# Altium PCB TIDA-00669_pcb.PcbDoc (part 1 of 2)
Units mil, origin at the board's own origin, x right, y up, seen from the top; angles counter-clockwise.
Board outline 2510.03 x 1760.03 mil, 2 copper layers (Top Layer, Bottom Layer), stack 62 mil thick; 109 components, 52 nets, 337 pads, 6 vias.
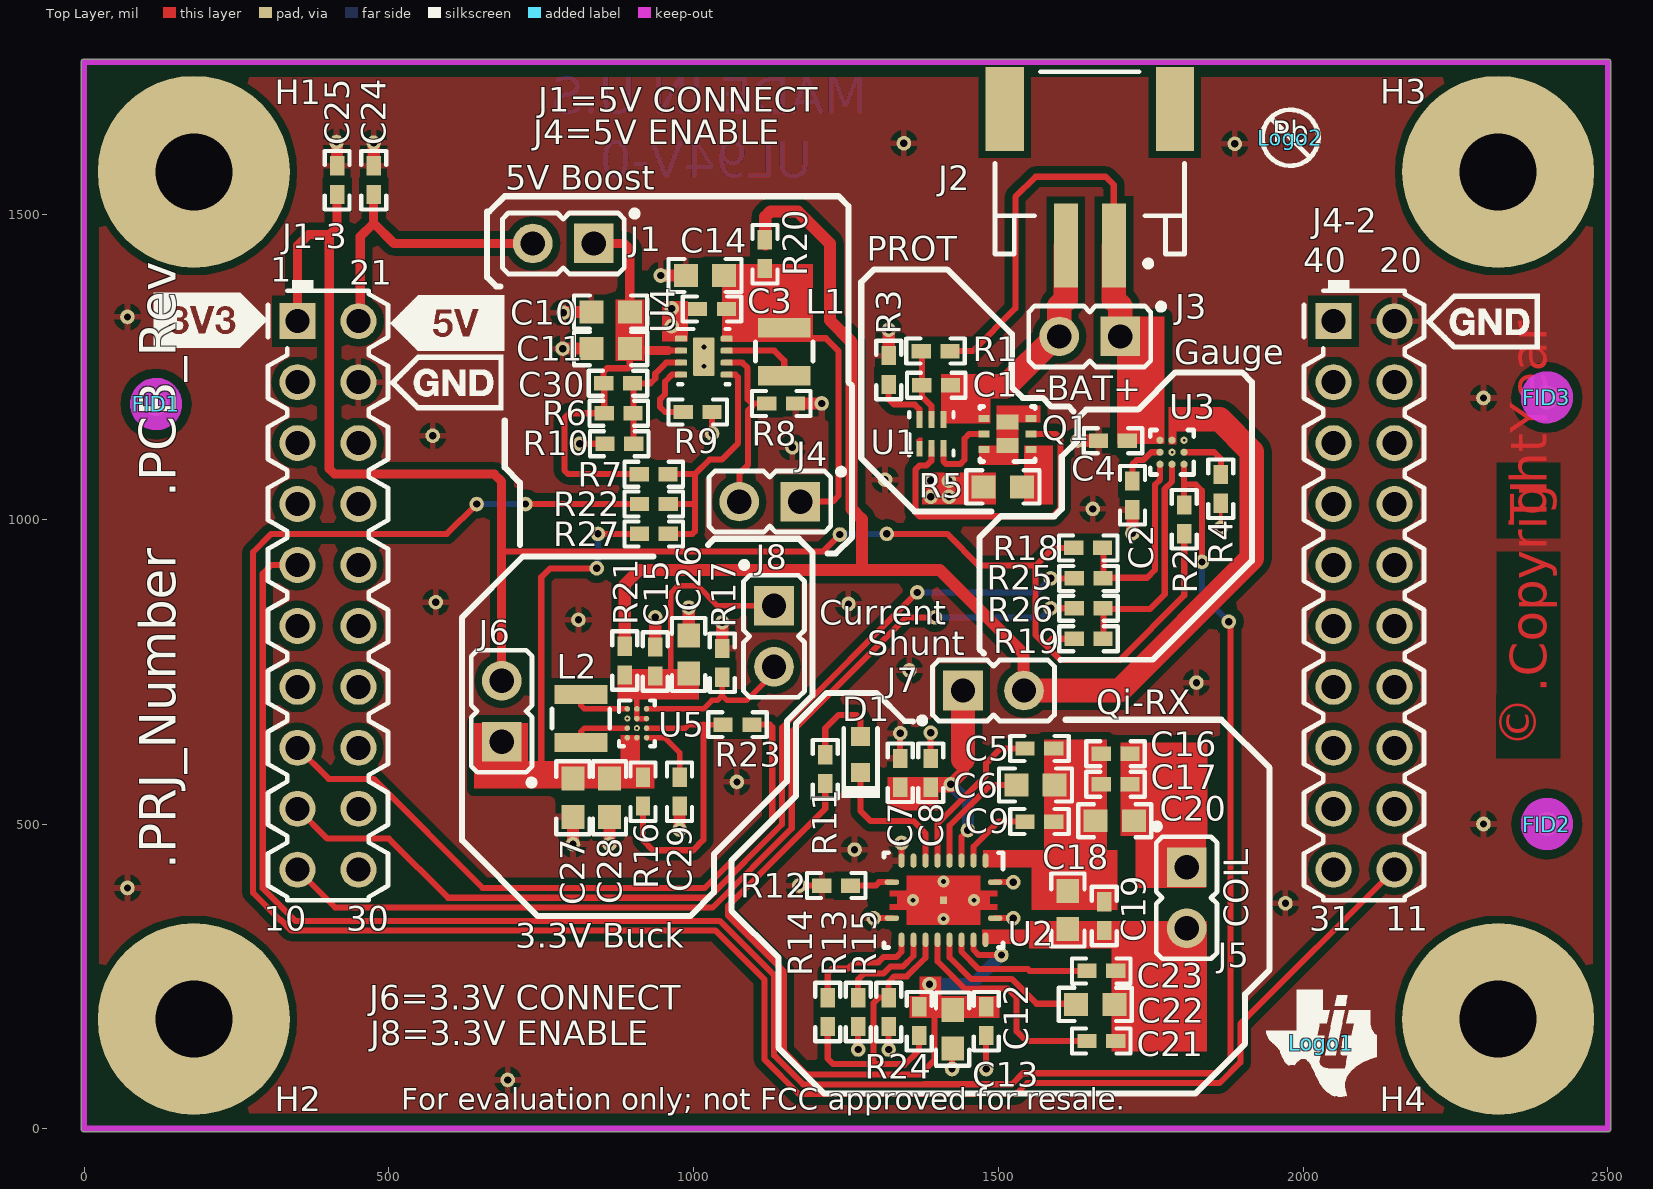
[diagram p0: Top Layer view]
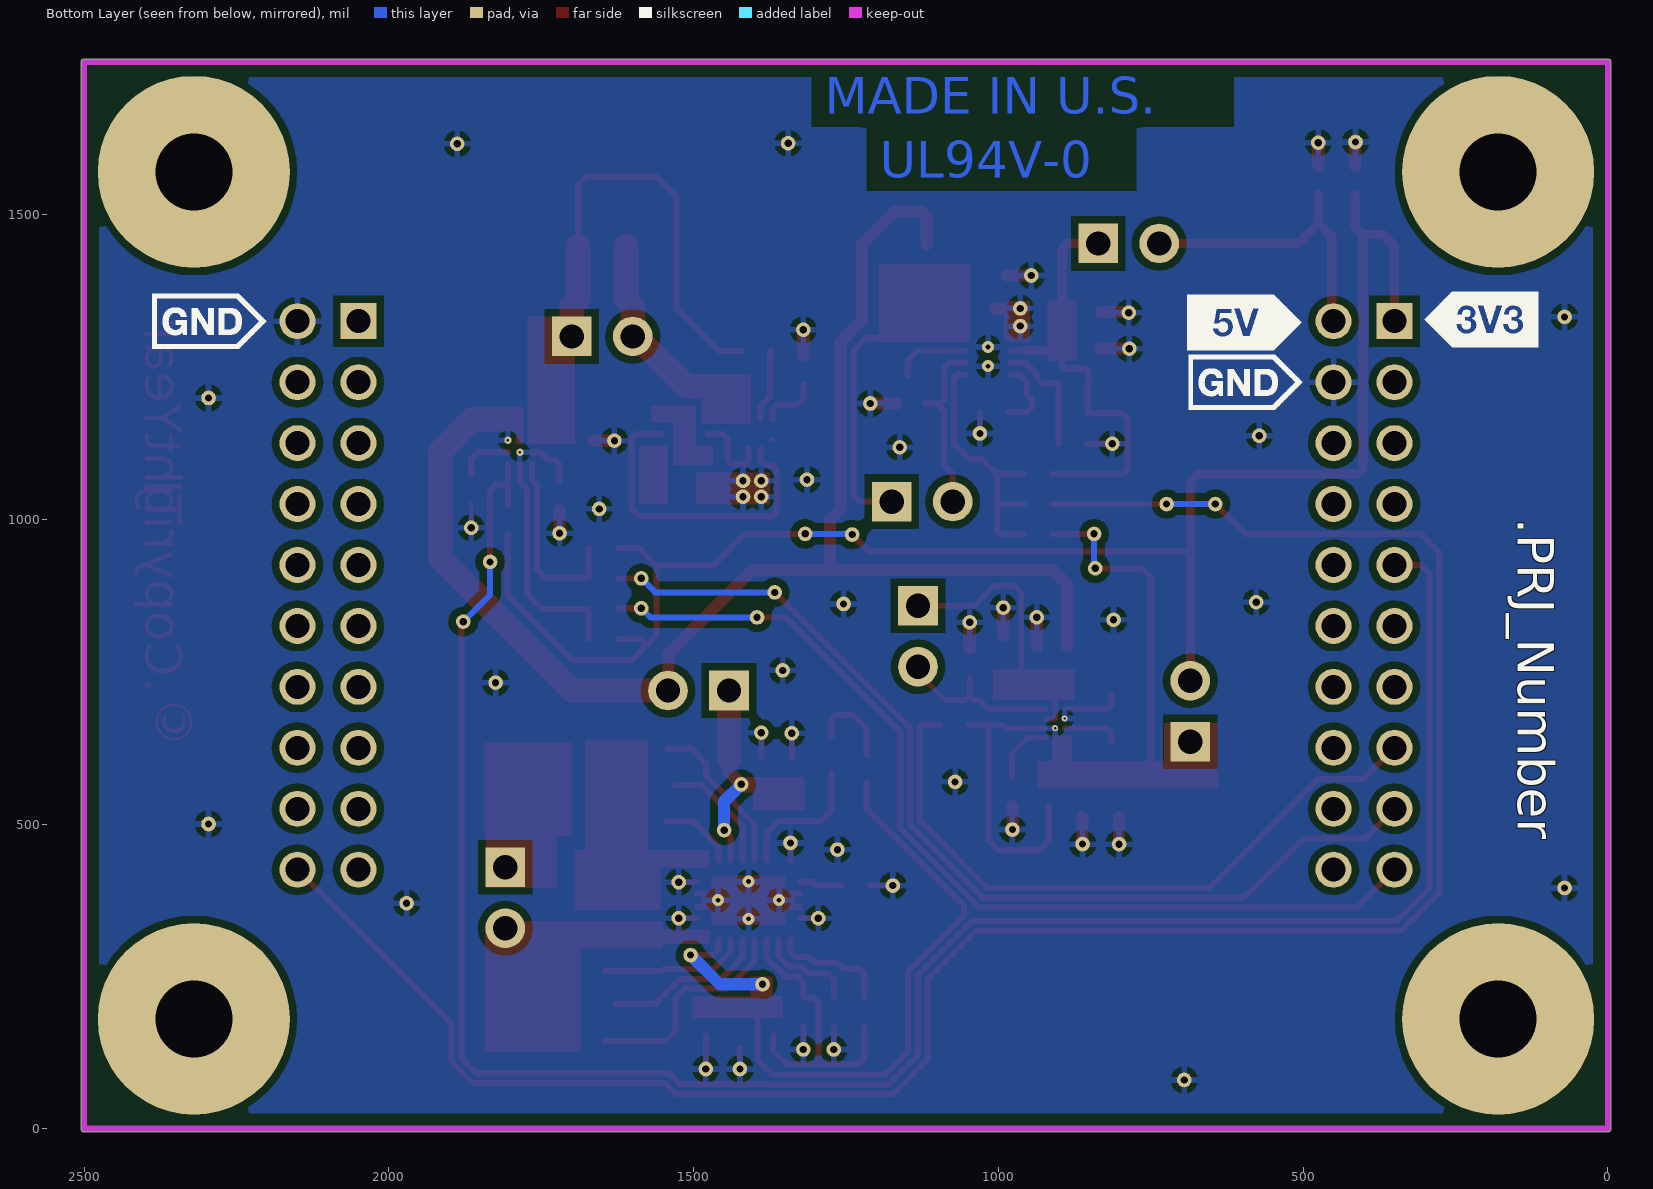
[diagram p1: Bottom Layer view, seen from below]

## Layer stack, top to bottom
Top Solder: solder mask 0.4, Solder Resist, Dk 3.5
Top Layer: signal copper 1.4
Dielectric1: core 59.2, FR-4, Dk 4.8
Bottom Layer: signal copper 1.4
Bottom Solder: solder mask 0.4, Solder Resist, Dk 3.5

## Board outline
0,-5.02 cw(c0,0) -5.01,0 -5.01,1750 cw(c0,1750) 0,1755.01 2500,1755.01 cw(c2500,1750) 2505.01,1750 2505.01,0 cw(c2500,0) 2500,-5.02

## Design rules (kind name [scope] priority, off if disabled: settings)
AcuteAngle [All] p1: minimum=4.50000000000000E+0001 checktracksonly=FALSE
AssemblyTestPointUsage [All] p1: valid=2
Clearance Clearance_Keepouts [((IsTrack Or IsArc) And Not InPoly) And IsFree and IsKeepOut vs ((IsTrack Or IsArc) And Not InPoly) And IsFree and IsKeepOut] p1: gap=0
Clearance Clearance_BoardEdge_MountingHoles [OnCopper and InComponentClass('Mounting Holes') vs IsKeepOut] p2: gap=15
Clearance Clearance_BoardEdge_Poly [OnCopper and InPoly vs IsKeepOut] p3: gap=15
Clearance Clearance_BoardEdge [OnCopper and Not InComponentClass('Logo') and not InComponentClass('FiducialMark') and not InRegion(1000,500,4000,800) and Not IsKeepout vs IsKeepOut] p4: gap=40
Clearance Clearance_Poly [InPolygon] p5: gap=12
Clearance [All] p6: gap=6
ComponentClearance ComponentClearance_MountingHoles_FiducialMarks [InComponentClass('Mounting Holes') vs InComponentClass('FiducialMark')] p1: gap=50 collisioncheckmode=3 verticalgap=10 showdistances=FALSE
ComponentClearance ComponentClearance_Shunt [InComponentClass('Header') vs InComponentClass('Shunt')] p2: gap=0 collisioncheckmode=3 verticalgap=0 showdistances=FALSE
ComponentClearance ComponentClearance_Logo [InComponentClass('Logo')] p3: gap=50 collisioncheckmode=3 verticalgap=10 showdistances=FALSE
ComponentClearance ComponentClearance_ScrewToNut [(HasFootprint('NY PMS 440 0025 PH')) vs (HasFootprint('Keystone_1902C'))] p4: gap=5 collisioncheckmode=3 verticalgap=10 showdistances=FALSE
ComponentClearance ComponentClearance_MountingHoles [InComponentClass('Mounting Holes')] p5: gap=20 collisioncheckmode=3 verticalgap=100000 showdistances=FALSE
ComponentClearance ComponentClearance_SmallPassives [HasFootprint('0201*') or HasFootprint('0402*') or HasFootprint('0508') or HasFootprint('0603*') or HasFootprint('0612') or HasFootprint('0805*') or HasFootprint('0815*') or HasFootprint('0830*') or HasFootprint('1206*') or HasFootprint('1210*') or HasFootprint('1808*') or HasFootprint('1812*') or HasFootprint('1825*') or HasFootprint('2010*') or HasFootprint('2220*') or HasFootprint('2225*') or HasFootprint('2512*') or HasFootprint('2728*') or HasFootprint('3518*') vs HasFootprint('0201*') or HasFootprint('0402*') or HasFootprint('0508') or HasFootprint('0603*') or HasFootprint('0612') or HasFootprint('0805*') or HasFootprint('0815*') or HasFootprint('0830*') or HasFootprint('1206*') or HasFootprint('1210*') or HasFootprint('1808*') or HasFootprint('1812*') or HasFootprint('1825*') or HasFootprint('2010*') or HasFootprint('2220*') or HasFootprint('2225*') or HasFootprint('2512*') or HasFootprint('2728*') or HasFootprint('3518*')] p6: gap=12 collisioncheckmode=3 verticalgap=12 showdistances=FALSE
ComponentClearance ComponentClearance_THtoSMT [IsThruComponent vs IsSMTComponent] p7: gap=12 collisioncheckmode=3 verticalgap=12 showdistances=FALSE
ComponentClearance ComponentClearance_THtoTH [IsThruComponent vs IsThruComponent] p8: gap=12 collisioncheckmode=3 verticalgap=12 showdistances=FALSE
ComponentClearance [All] p9: gap=12 collisioncheckmode=3 verticalgap=12 showdistances=FALSE
DiffPairsRouting [All] p1: maxlimit=100 minlimit=10 mostfreqgap=10 toplayer_minwidth=15 toplayer_maxwidth=15 toplayer_prefwidth=15 bottomlayer_minwidth=15 bottomlayer_maxwidth=15 bottomlayer_prefwidth=15 maxuncoupledlength=1000
FabricationTestPointUsage TestPointUsage [All] p1: valid=2 allowmultiple=FALSE
FabricationTestpoint Testpoint [All] p1: side=3 testpointundercomponent=TRUE minsize=40 maxsize=100 preferedsize=60 minholesize=0 maxholesize=40 preferedholesize=32 testpointgrid=1 allowsidetop=TRUE allowsidebottom=TRUE usegrid=TRUE gridtolerance=0.01
FanoutControl Fanout_LCC [IsLCC] p1: bgadir=Out bgaviamode=Centered fanoutstyle=Auto fanoutdirection=Alternating viagrid=1 // Fanout_LCC (Default Rule)
FanoutControl Fanout_BGA [IsBGA] p2: bgadir=Out bgaviamode=Centered fanoutstyle=Auto fanoutdirection=Alternating viagrid=1 // Fanout_BGA (Default Rule)
FanoutControl Fanout_Default [All] p4: bgadir=Out bgaviamode=Centered fanoutstyle=Auto fanoutdirection=Alternating viagrid=1 // Fanout_Default (Default Rule)
FanoutControl Fanout_Small [(CompPinCount < 5)] p5: bgadir=Out bgaviamode=Centered fanoutstyle=Auto fanoutdirection=OutThenIn viagrid=1 // Fanout_Small (Default Rule)
HoleSize [All] p1: absolutevalues=TRUE maxlimit=251 minlimit=8 maxpercent=80.000 minpercent=20.000
MinimumAnnularRing MinimumAnnularRing_ThermalPadVias [IsVia and InAnyComponent] p1: minimumring=5.91
MinimumAnnularRing [All] p2: minimumring=9
MinimumSolderMaskSliver MinimumSolderMaskSliver_Logo [InComponentClass('Logo') vs InComponentClass('Logo')] p1: minsoldermaskwidth=0.7
MinimumSolderMaskSliver [All] p2: minsoldermaskwidth=3.94
PlaneConnect [All] p1: planeconnectstyle=Relief reliefexpansion=10 reliefentries=4 reliefconductorwidth=10 reliefairgap=10
PolygonConnect [All] p1: connectstyle=Relief reliefconductorwidth=10 reliefentries=4 polygonreliefangle="90 Angle" airgapwidth=10
RoutingVias ThermalPadVias [IsVia and InAnyComponent] p1: holewidth=7.87 width=19.68 viastyle="Through Hole" minholewidth=7.87 minwidth=19.68 maxholewidth=12.99 maxwidth=23.62
RoutingVias [All] p2: holewidth=16 width=34 viastyle="Through Hole" minholewidth=7.87 minwidth=26 maxholewidth=40 maxwidth=65
SilkToBoardRegionClearance [Not ((IsComment or IsDesignator) And (Hide <> 'False')) and not InRegion(1000,500,4000,800)] p1:
SilkToSilkClearance SilkToSilkClearance_Pb-FreeLogo [(HasFootprint('Pb-Free_Overlay_Medium') OR HasFootprint('Pb-Free_Overlay_Small')) vs (HasFootprint('Pb-Free_Overlay_Medium') OR HasFootprint('Pb-Free_Overlay_Small'))] p1: silktosilkclearance=0
SilkToSilkClearance [All] p2: silktosilkclearance=5
SilkToSolderMaskClearance "Silk to Solder Mask Opening" [All] p1: minsilkscreentomaskgap=1 clearancetoexposedcopper=FALSE
SolderMaskExpansion [All] p1: expansion=1.97
UnpouredPolygon [All] p1: allowunpoured=FALSE
Width [All] p1: maxlimit=100 minlimit=6 preferedwidth=10 checkconnectedcopper=TRUE
14 further rules are at their usual default settings.

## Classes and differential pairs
component class EMI: "Coil 1" "Ferrite 1"
component class AssemblyNote: ZZ1 ZZ2 ZZ3 ZZ4 ZZ5 ZZ6 ZZ7 ZZ8
component class FiducialMark: FID1 FID2 FID3
component class TIDA-00669_hdw: "Coil 1" "Ferrite 1" FID1 FID2 FID3 H1 H2 H3 H4 H5 H6 H7 H8 HS1 HS2 HS3 HS4 Logo1 Logo2 Logo3 SH-J1 SH-J4 SH-J6 SH-J7 SH-J8 ZZ1 ZZ2 ZZ3 ZZ4 ZZ5 ZZ6 ZZ7 ZZ8
component class Logo: Logo1
component class TIDA-00669_sch: C1 C2 C3 C4 C5 C6 C7 C8 C9 C10 C11 C12 C13 C14 C15 C16 C17 C18 C19 C20 C21 C22 C23 C24 C25 C26 C27 C28 C29 C30 D1 J1 J1-3 J2 J3 J4 J4-2 J5 J6 J7 J8 L1 L2 Q1 R1 R2 R3 R4 R5 R6 R7 R8 R9 R10 R11 R12 R13 R14 R15 R16 R17 R18 R19 R20 R21 R22 R23 R24 R25 R26 R27 U1 U2 U3 U4 U5
component class Header: J1 J1-3 J3 J4 J4-2 J5 J6 J7 J8
component class "Mounting Holes": H1 H2 H3 H4 H5 H6 H7 H8
component class Shunt: SH-J1 SH-J4 SH-J6 SH-J7 SH-J8

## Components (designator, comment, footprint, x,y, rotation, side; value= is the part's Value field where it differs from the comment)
C1 "GRM155R71A104KA01D" 0402 1398,1220 r0 top
C2 "GRM155R60J474KE19D" 0402 1720,1039.38 r270 top
C3 "GRM155R71A104KA01D" 0402 1030.08,1345 r180 top
C4 "GRM155R61A105KE15D" 0402 1688,1129 r180 top
C5 "GRM155R71H223KA12D" 0402 1567.38,623.94 r0 top
C6 "GRM188R71E474KA12D" 0603 1560.88,563.94 r0 top
C7 "GRM155R71A104KA01D" 0402 1338.94,583.94 r90 top
C8 "C1005X5R1A475K050BC" 0402 1388.94,583.94 r90 top
C9 "C0402C103J5RACTU" 0402 1567.38,503.94 r0 top
C10 "C0603C106M9PACTU" 0603 863.7,1340 r180 top
C11 "C0603C106M9PACTU" 0603 863.7,1280 r180 top
C12 "C1005X7R1C223K" 0402 1480,176.38 r270 top
C13 "GRM188R61C475KAAJ" 0603 1425,163.5 r270 top
C14 "C0603C106M9PACTU" 0603 1018.7,1400 r180 top
C15 "GRM155R71A104KA01D" 0402 936.92,766.7 r90 top
C16 "C1005X7R1H683K" 0402 1692.38,615.26 r0 top
C17 "C1005X7R1H683K" 0402 1692.38,565.26 r0 top
C18 "GRM1885C1H182JA01D" 0603 1613.94,358.94 r270 top
C19 "CC0402JRNPO9BN101" 0402 1673.94,348.94 r90 top
C20 "GRM188R71H473KA61D" 0603 1690.88,505.26 r0 top
C21 "GRM155R71H223KA12D" 0402 1668.94,143.94 r0 top
C22 "GRM188R71E474KA12D" 0603 1658.94,203.94 r0 top
C23 "C0402C103J5RACTU" 0402 1668.94,258.94 r0 top
C24 "GRM155R71A104KA01D" 0402 475,1556.38 r90 top
C25 "GRM155R71A104KA01D" 0402 415,1556.38 r90 top
C26 "C0603C106M9PACTU" 0603 991.92,778.08 r90 top
C27 "C0603C106M9PACTU" 0603 801.92,543.08 r270 top
C28 "C0603C106M9PACTU" 0603 861.92,543.08 r270 top
C29 "0402YC132KAT2A" 0402 976.92,553.08 r270 top
C30 "CC0402JRNPO9BN101" 0402 876,1223 r0 top
"Coil 1" "760308103206" SIL-PAD_24X21MM 1500,7360 r90 top
D1 "LTST-C190GKT" LED_LTST-C190 1273.94,613.94 r270 top
"Ferrite 1" "354005" SIL-PAD_24X21MM 2440,7370 r90 top
FID1 "Fiducial" Fiducial10-20 118,1189 r0 top
FID2 "Fiducial" Fiducial10-20 2400,500 r0 top
FID3 "Fiducial" Fiducial10-20 2400,1200 r0 top
H1 "NY PMS 440 0025 PH" "NY PMS 440 0025 PH" 180,1570 r0 top locked
H2 "NY PMS 440 0025 PH" "NY PMS 440 0025 PH" 180,180 r0 top locked
H3 "NY PMS 440 0025 PH" "NY PMS 440 0025 PH" 2320,1570 r0 top locked
H4 "NY PMS 440 0025 PH" "NY PMS 440 0025 PH" 2320,180 r0 top locked
H5 "NY PMS 440 0025 PH" "NY PMS 440 0025 PH" 1150.36,3190 r180 top
H6 "NY PMS 440 0025 PH" "NY PMS 440 0025 PH" 128.36,3186 r180 top
H7 "NY PMS 440 0025 PH" "NY PMS 440 0025 PH" 468.36,3186 r180 top
H8 "NY PMS 440 0025 PH" "NY PMS 440 0025 PH" 818.36,3186 r180 top
HS1 "1902B" Keystone_1902B 200,2750 r0 top
HS2 "1902B" Keystone_1902B 550,2750 r0 top
HS3 "1902B" Keystone_1902B 900,2750 r0 top
HS4 "1902B" Keystone_1902B 1250,2750 r0 top
J1 "PBC02SAAN" Sullins_PBC02SAAN 786.16,1452.58 r270 top
J1-3 "PRPC010DAAN-RC" Sullins_xxxC010DAAN 400,875 r0 top
J2 "S2B-PH-SM4-TB(LF)(SN)" JST_S2B-PH-SM4-TB 1650,1565 r180 top
J3 "PBC02SAAN" Sullins_PBC02SAAN 1650,1300 r270 top
J4 "PBC02SAAN" Sullins_PBC02SAAN 1125,1029 r270 top
J4-2 "PRPC010DAAN-RC" Sullins_xxxC010DAAN 2100,875 r0 top
J5 "PBC02SAAN" Sullins_PBC02SAAN 1808.94,378.94 r0 top
J6 "PBC02SAAN" Sullins_PBC02SAAN 685,685 r180 top
J7 "PBC02SAAN" Sullins_PBC02SAAN 1492,719 r90 top
J8 "PBC02SAAN" Sullins_PBC02SAAN 1131.92,808.08 r0 top
L1 "LQM2HPN1R5MG0L" 1008 1148.7,1275 r270 top
L2 "LQM2HPN1R5MG0L" 1008 815,673 r270 top
Logo1 "Texas Instruments" TI_Symbol_Overlay_Small 2030,140 r0 top
Logo2 "Pb-Free Symbol" Pb-Free_Overlay_Small 1979,1626 r0 top
Logo3 "FCC disclaimer" FCC_disclaimer 150,-560 r90 top
Q1 "CSD85301Q2" DQK0006B 1515,1140 r180 top
R1 "CRCW0402221RFKED" 0402 1397,1276 r0 top
R2 "CRCW040210K0FKED" 0402 1805,1000 r270 top
R3 "CRCW04022K21FKED" 0402 1320,1245 r270 top
R4 "CRCW040210K0FKED" 0402 1865,1050 r90 top
R5 "ERJ-L03KF47MV" 0603 1507.5,1053 r0 top
R6 "CRCW0402768KFKED" 0402 877,1174 r180 top
R7 "CRCW04021M00FKED" 0402 934.38,1074 r180 top
R8 "CRCW04021M00FKED" 0402 1143.7,1190 r180 top
R9 "CRCW040212K4FKED" 0402 1006.62,1176 r0 top
R10 "CRCW0402243KFKED" 0402 878,1124 r0 top
R11 "CRCW04021K50FKED" 0402 1216,590 r270 top
R12 "CRCW04022K43FKED" 0402 1233.94,398.94 r0 top
R13 "CRCW040210K0FKED" 0402 1270,191.38 r90 top
R14 "CRCW0402422RFKED" 0402 1220,191.38 r90 top
R15 "CRCW0402200RFKED" 0402 1320,191.38 r90 top
R16 "CRCW04021M00FKED" 0402 916.92,553.08 r270 top
R17 "CRCW04021M00FKED" 0402 1046.92,764.46 r270 top
R18 "CRCW04021K00FKED" 0402 1647.38,953 r180 top
R19 "CRCW04021K00FKED" 0402 1648,804 r180 top
R20 "CRCW04020000Z0ED" 0402 1117,1435 r270 top
R21 "CRCW04020000Z0ED" 0402 886.92,768.08 r270 top
R22 "CRCW04020000Z0ED" 0402 934.62,1025 r180 top
R23 "CRCW04020000Z0ED" 0402 1071.92,663.08 r0 top
R24 "CRCW040220K0FKED" 0402 1370,176.38 r90 top
R25 "CRCW04020000Z0ED" 0402 1648,903 r180 top
R26 "CRCW04020000Z0ED" 0402 1648,854 r180 top
R27 "CRCW04021M00FKED" 0402 934.62,976 r0 top
SH-J1 "969102-0000-DA" SNT-100-BK-G 120,3640 r90 top
SH-J4 "969102-0000-DA" SNT-100-BK-G 470,3640 r90 top
SH-J6 "969102-0000-DA" SNT-100-BK-G 820,3640 r90 top
SH-J7 "969102-0000-DA" SNT-100-BK-G 1170,3640 r90 top
SH-J8 "969102-0000-DA" SNT-100-BK-G 1520,3640 r90 top
U1 "BQ29707DSER" DSE0006A 1390,1140 r90 top
U2 "BQ51050BRHL" RHL0020A 1410,375 r270 top
U3 "BQ27421YZFR-G1A" YZF0009AKAL 1785,1110 r180 top
U4 "TPS61252DSG" DSG0008A 1016.8,1266.86 r0 top
U5 "TPS63051YFF" YFF0012AFAF 906.92,665.21 r0 top
ZZ1 "These assemblies are ESD sensitive, ESD precautions shall be observed." AssemblyNote 1125,6730 r0 top
ZZ2 "These assemblies must be clean and free from flux and all contaminants. Use of no clean flux is not acceptable." AssemblyNote 1095,6635 r0 top
ZZ3 "These assemblies must comply with workmanship standards IPC-A-610 Class 2, unless otherwise specified." AssemblyNote 1100,6540 r0 top
ZZ4 "Wireless Coil 1 will be attached to the PCB C02 on the bottom of the board stack. The wires will be soldered to the PCB." AssemblyNote 1145,6460 r0 top
ZZ5 "The Ferrite Shield must be custom cut to fit the PCB. Only the four mounting holes are allowed." AssemblyNote 1120,6330 r0 top
ZZ6 "Nylon screws and spacers only for this assembly. The only copper on PCB C01 and C02 is for the wire holes. No extra copper is allowed on PCB C01 and C02." AssemblyNote 1105,6245 r0 top
ZZ7 "Use 2 strands, 3 inch Length, of 26 gauge litz wire to connect the PCB C01 board to the main PCB connector J3. Attach the litz wire to PCB C02 and leave hanging." AssemblyNote 1150,6130 r0 top
ZZ8 "The assembly build will use PCB C01. Bag and ship PCB C02 with the assembly." AssemblyNote 1145,6010 r0 top

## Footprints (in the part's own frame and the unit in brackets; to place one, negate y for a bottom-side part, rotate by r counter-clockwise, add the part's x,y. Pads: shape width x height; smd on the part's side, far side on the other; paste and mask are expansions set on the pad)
0402 [mm] "0402 from SM-752 data"
  rect 0.8x0.6 smd: 1(-0.6,0) 2(0.6,0)
  silkscreen extent -1.22,-0.52 1.22,0.52, body extent -0.55,-0.3 0.55,0.3, height 0.6
0603 [mm] "0603 from SM-752 data"
  rect 1x0.95 smd: 1(-0.8,0) 2(0.8,0)
  silkscreen extent -1.52,-0.69 1.52,0.69, body extent -0.87,-0.47 0.87,0.47, height 0.85
1008 [mm] "SMD, Body 2.5x2mm, Height 1.2mm"
  rect 0.8x2.2 smd: 1(-1,0) 2(1,0)
  silkscreen extent -0.4,-1.2 0.4,1.2, body extent -1.35,-1.1 1.35,1.1, height 1.2
AssemblyNote [mil] "Assembly Note"
DQK0006B [mm] "TI"
  rect 0.45x0.3 smd: 1(-0.975,0.65) 2(-0.975,0) 3(-0.975,-0.65) 4(0.975,-0.65) 5(0.975,0) 6(0.975,0.65)
  rect 0.9x0.625 smd paste-0.025: 7(0,0.488) 8(0,-0.488)
  silkscreen extent -1.15,-1.15 1.15,1.15, body extent -1.05,-1.05 1.05,1.05, height 0.8
DSE0006A [mm] "TI recommended land pattern"
  rect 0.66x0.25 smd: 1(-0.62,0.5)
  rect 0.7x0.25 smd: 2(-0.6,0) 3(-0.6,-0.5) 4(0.6,-0.5) 5(0.6,0) 6(0.6,0.5)
  Top Layer region: -0.3,0.625 -0.25,0.625 -0.15,0.525 -0.15,0.375 -0.3,0.375
  silkscreen extent -0.9,-0.92 0.9,0.92, body extent -0.77,-0.77 0.77,0.77, height 0.8
DSG0008A [mm] "SON, 8-Leads, Body 2x2mm, Pitch 0.5mm, Thermal Pad 1.6x0.9mm, TI Recommended"
  rrect40% 0.5x0.25 smd: 1(-0.95,0.75) 2(-0.95,0.25) 3(-0.95,-0.25) 4(-0.95,-0.75) 5(0.95,-0.75) 6(0.95,-0.25) 7(0.95,0.25) 8(0.95,0.75)
  rrect11% 0.9x1.6 smd paste-0.45: 9(0,0)
  silkscreen extent -1.07,-1.15 1.07,1.15, body extent -1.05,-1.05 1.05,1.05, height 0.8
FCC_disclaimer [mil]
Fiducial10-20 [mm]
  round 1 smd mask+0.5: 1(0,0)
  Top Layer keep-out circle w1.178: c0,0 r0.5
JST_S2B-PH-SM4-TB [mm] "JST Sales America Inc"
  rect 1x3.5 smd paste+0 mask+0.05: 1(-1,2.95) 2(1,2.95)
  rect 1.6x3.5 smd paste+0 mask+0.05: M1(-3.55,-2.75) M2(3.55,-2.75)
  silkscreen extent -3.95,-4.3 3.95,3.79, body extent -3.95,-4.3 3.95,4.3, height 5.62
Keystone_1902B [mil] "Hex Standoff, 4-40 threaded, nylon"
  round 1 on Mech3: 0(0,0)
  body extent -145,-126 145,126, height 375
LED_LTST-C190 [mm] "Lite-On"
  rect 0.8x0.8 smd: 1(-0.75,0) 2(0.75,0)
  silkscreen extent -1.1,-0.8 1.8,0.8, body extent -0.85,-0.45 0.85,0.45, height 0.9
"NY PMS 440 0025 PH" [mm] "4-40 nylon screw and mounting hole"
  round 8 hole 3.2: 1(0,0)
  body extent -3.3,-3.3 3.3,3.3, height 2.69
Pb-Free_Overlay_Small [mil]
  silkscreen extent -46,-46 46,46
RHL0020A [mm] "QFN, 20-Leads, Body 4.5x3.5mm, Pitch 0.5mm, Thermal Pad 3.05x2.05mm, TI Recommended"
  oval 0.24x0.6 smd: 1(-0.75,2.15) 10(-0.75,-2.15) 11(0.75,-2.15) 20(0.75,2.15)
  oval 0.6x0.24 smd: 2(-1.65,1.75) 3(-1.65,1.25) 4(-1.65,0.75) 5(-1.65,0.25) 6(-1.65,-0.25) 7(-1.65,-0.75) 8(-1.65,-1.25) 9(-1.65,-1.75) 12(1.65,-1.75) 13(1.65,-1.25) 14(1.65,-0.75) 15(1.65,-0.25) 16(1.65,0.25) 17(1.65,0.75) 18(1.65,1.25) 19(1.65,1.75)
  rect 0.3x0.3 smd paste-0.15 mask+0: 21(0,0)
  Top Layer region: 0.16,2.25 0.16,1.925 -0.16,1.925 -0.16,2.25 -0.39,2.25 -0.39,1.525 -1.025,1.525 -1.025,-1.525 -0.39,-1.525 -0.39,-2.25 -0.16,-2.25 -0.16,-1.925 0.16,-1.925 0.16,-2.25 0.39,-2.25 0.39,-1.525 1.025,-1.525 1.025,1.525 0.39,1.525 0.39,2.25
  silkscreen extent -1.98,-2.47 1.98,2.47, body extent -1.82,-2.33 1.83,2.32, height 1.01
SIL-PAD_24X21MM [mil] "Sil-Pad"
  silkscreen extent -482,-423 482,423, body extent -472,-413 472,413, height 9
SNT-100-BK-G [mil] "Samtec STEP model"
  round 1 on Mech3: 0(0,0)
  body extent -100,-50 100,50, height 344
Sullins_PBC02SAAN [mm] "Sullins 100mil, 1x2, 230 mil above insulator"
  rect 1.65x1.65 hole 1.016: 1(0,1.27)
  round 1.65 hole 1.016: 2(0,-1.27)
  silkscreen extent -1.37,-2.54 1.27,3.1, body extent -1.27,-2.54 1.27,2.54, height 8.38
Sullins_xxxC010DAAN [mm] "Header, 2.54mm, 10x2, TH"
  rect 1.5x1.5 hole 1: 1(-1.27,11.43)
  round 1.5 hole 1: 2(1.27,11.43) 3(-1.27,8.89) 4(1.27,8.89) 5(-1.27,6.35) 6(1.27,6.35) 7(-1.27,3.81) 8(1.27,3.81) 9(-1.27,1.27) 10(1.27,1.27) 11(-1.27,-1.27) 12(1.27,-1.27) 13(-1.27,-3.81) 14(1.27,-3.81) 15(-1.27,-6.35) 16(1.27,-6.35) 17(-1.27,-8.89) 18(1.27,-8.89) 19(-1.27,-11.43) 20(1.27,-11.43)
  silkscreen extent -2.5,-12.7 2.5,13.14, body extent -2.5,-12.7 2.5,12.7, height 8.34
TI_Symbol_Overlay_Small [mil]
  silkscreen extent -90,-88 91,88
YFF0012AFAF [mm] "TI DSBGA 1.716x1.316mm"
  round 0.23 smd paste-0.13 mask+0.038: A1(-0.4,0.6) A2(0,0.6) A3(0.4,0.6) B1(-0.4,0.2) B2(0,0.2) B3(0.4,0.2) C1(-0.4,-0.2) C2(0,-0.2) C3(0.4,-0.2) D1(-0.4,-0.6) D2(0,-0.6) D3(0.4,-0.6)
  silkscreen extent -0.75,-0.95 0.75,0.95, body extent -0.66,-0.86 0.66,0.86, height 0.63
YZF0009AKAL [mm] "BGA, 9-Leads, Body 1.6205x1.58mm, Pitch 0.5mm"
  round 0.3 smd paste-0.15 mask+0.05: A1(-0.5,0.5) A2(0,0.5) A3(0.5,0.5) B1(-0.5,0) B2(0,0) B3(0.5,0) C1(-0.5,-0.5) C2(0,-0.5) C3(0.5,-0.5)
  silkscreen extent -0.9,-0.93 0.9,0.93, body extent -0.8,-0.83 0.8,0.83, height 0.63

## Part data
C1 C3 C7 C15 C24 C25: "CAP, CERM, 0.1 µF, 10 V, +/- 10%, X7R, 0402"
C2: "CAP, CERM, 0.47 µF, 6.3 V, +/- 10%, X5R, 0402"
C4: "CAP, CERM, 1 µF, 10 V, +/- 10%, X5R, 0402"
C5 C21: "CAP, CERM, 0.022 µF, 50 V, +/- 10%, X7R, 0402"
C6 C22: "CAP, CERM, 0.47 µF, 25 V, +/- 10%, X7R, 0603"
C8: "CAP, CERM, 4.7 µF, 10 V, +/- 10%, X5R, 0402"
C9 C23: "CAP, CERM, 0.01 µF, 50 V, +/- 5%, X7R, 0402"
C10 C11 C14 C26 C27 C28: "CAP, CERM, 10 µF, 6.3 V, +/- 20%, X5R, 0603"
C12: "CAP, CERM, 0.022 µF, 16 V, +/- 10%, X7R, 0402"
C13: "CAP, CERM, 4.7 µF, 16 V, +/- 10%, X5R, 0603"
C16 C17: "CAP, CERM, 0.068 µF, 50 V, +/- 10%, X7R, 0402"
C18: "CAP, CERM, 1800 pF, 50 V, +/- 5%, C0G/NP0, 0603"
C19 C30: "CAP, CERM, 100 pF, 50 V, +/- 5%, C0G/NP0, 0402"
C20: "CAP, CERM, 0.047 µF, 50 V, +/- 10%, X7R, 0603"
C29: "CAP, CERM, 1300 pF, 16 V, +/- 10%, X7R, 0402"
"Coil 1": library part SP900S-0.009-00-114, "Wireless coil"
D1: "LED, Green, SMD"
"Ferrite 1": library part SP900S-0.009-00-114, "Ferrite shield"
FID1 FID2 FID3: "Fiducial mark.  There is nothing to buy or mount."
H1 H2 H3 H4 H5 H6 H7 H8: "Machine Screw, Round, #4-40 x 1/4, Nylon, Philips panhead"
HS1 HS2 HS3 HS4: "Standoff, Hex, 0.375\"L #4-40 Nylon"
J1 J3 J4 J5 J6 J7 J8: "Header, 100mil, 2x1, Gold, TH"
J1-3 J4-2: "Header, 2.54mm, 10x2, Gold, TH"
J2: "Header (shrouded), 2mm, 2x1, R/A, SMT"
L1 L2: "Inductor, Multilayer, Ferrite, 1.5 µH, 1.5 A, 0.07 ohm, SMD"
Logo1: library part TI_Logo, "Texas Instrument Corporate Signature"
Logo2: library part Pb-Free
Logo3: library part FCC_disclaimer, "FCC_disclaimer"
Q1: "MOSFET, N-CH, 20 V, 6.7 A,"
R1: "RES, 221, 1%, 0.063 W, 0402"
R2 R4 R13: "RES, 10.0 k, 1%, 0.063 W, 0402"
R3: "RES, 2.21 k, 1%, 0.063 W, 0402"
R5: "RES, 0.047, 1%, 0.1 W, 0603"
R6: "RES, 768 k, 1%, 0.063 W, 0402"
R7 R8 R16 R17 R27: "RES, 1.00 M, 1%, 0.063 W, 0402"
R9: "RES, 12.4 k, 1%, 0.063 W, 0402"
R10: "RES, 243 k, 1%, 0.063 W, 0402"
R11: "RES, 1.50 k, 1%, 0.063 W, 0402"
R12: "RES, 2.43 k, 1%, 0.063 W, 0402"
R14: "RES, 422, 1%, 0.063 W, 0402"
R15: "RES, 200, 1%, 0.063 W, 0402"
R18 R19: "RES, 1.00 k, 1%, 0.063 W, 0402"
R20 R21 R22 R23 R25 R26: "RES, 0, 5%, 0.063 W, 0402"
R24: "RES, 20.0 k, 1%, 0.063 W, 0402"
SH-J1 SH-J4 SH-J6 SH-J7 SH-J8: "Shunt, 100mil, Gold plated, Black"
U1: library part BQ29700DSER, "Cost-Effective Voltage and Current Protection Integrated Circuit for Single-Cell Li-Ion/Li-Polymer Batteries, DSE0006A"
U2: "High-Efficiency Qi v1.1-Compliant Wireless Power Receiver and Battery Charger, RHL0020A"
U3: "System-Side Impedance Track Fuel Gauge With Integrated Sense Resistor, YZF0009AKAL"
U4: "TINY 1.5-A BOOST CONVERTER WITH ADJUSTABLE INPUT CURRENT LIMIT, DSG0008A"
U5: "SINGLE INDUCTOR BUCK-BOOST WITH 1A SWITCHES AND ADJUSTABLE SOFT START, YFF0012AFAF"
ZZ1 ZZ2 ZZ3 ZZ4 ZZ5 ZZ6 ZZ7 ZZ8: library part AssemblyNote

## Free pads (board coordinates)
  round 24 hole 12: 0(71,395) 0(71,1332) 0(414,1619) 0(475,1618) 0(572,1137) 0(577,864) 0(644,1025) 0(695,80) 0(724,1025) 0(785,1280) 0(786,1339) 0(802,467) 0(811,835) 0(813,1124) 0(841,919.53) 0(843,976) 0(861.92,467.08) 0(936.92,839.08) 0(946,1400) 0(964,1317) 0(964,1346) 0(976.92,490.92) 0(991.92,855.08) 0(1030.24,1140.76) 0(1046.92,830.92) 0(1071,569) 0(1162,1118) 0(1173.06,398.94) 0(1210,1190) 0(1240,975) 0(1254,861) 0(1264,458) 0(1270,130) 0(1295.47,345.47) 0(1314,1065) 0(1317,976) 0(1320,130) 0(1320,1311) 0(1338.94,648.94) 0(1341.1,468.9) 0(1345,1617) 0(1354,752) 0(1367,880) 0(1387,237) 0(1388.94,649.94) 0(1389,1037) 0(1389,1063) 0(1396,839) 0(1419,1037) 0(1419,1063) 0(1422,565) 0(1424,98) 0(1450,490) 0(1480,98) 0(1505,285) 0(1524.52,404.52) 0(1524.53,345.47) 0(1586,854) 0(1586,903) 0(1630,1129) 0(1655,1017) 0(1720,977) 0(1825,732) 0(1834,930) 0(1865,986) 0(1878,832) 0(1888,1616) 0(1971,370) 0(2296,500) 0(2296,1199)
  round 10 hole 4: 0(891.17,673.08) 0(906.92,657.33)
  round 12 hole 4: 0(1785,1110) 0(1804.68,1129.68)

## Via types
v1: diameter 19.68, hole 7.87, Top Layer to Bottom Layer, 6 vias

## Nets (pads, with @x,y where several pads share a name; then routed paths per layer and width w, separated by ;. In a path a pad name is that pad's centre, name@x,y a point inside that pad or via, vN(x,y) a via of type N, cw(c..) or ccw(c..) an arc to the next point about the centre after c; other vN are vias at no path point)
+3.3V: C25.1 J1-3.1 J6.2 pad.0@1240,975 pad.0@1317,976 R2.2 R18.2 R19.2 | length 2811.7
  Top Layer w10: 685,947 1212,947 1234,969 pad.0@1240,975 ; pad.0@1317,976 1416,976 1468,924 1561,924 ; R18.2@1623.76,953 1590,953 1561,924 ; R19.2@1624.38,804 1588,804 1577.5,793.5 ; R2.2@1805,976.38 1805,875 1699,769 1602,769 1577.5,793.5 ; 1561,924 1561,810 1577.5,793.5
  Top Layer w15: J1-3.1@350,1325 350,1449 368,1467 402,1467 ; C25.1@415,1532.76 415,1480 402,1467 ; J6.2@685,735 685,947 685,1062 673,1074 411,1074 402,1083 402,1467
  Bottom Layer w10: pad.0@1241,976 pad.0@1317,976
+5V: C24.1 J1-3.2 J1.2 | length 493.1
  Top Layer w15: J1-3.2@450,1325 453,1328 453,1464 475,1486 ; C24.1@475,1532.76 475,1486 ; J1.2@736.16,1452.58 508.42,1452.58 475,1486
BAT: C4.1 J2.1 J3.1 R1.2 U3.C3 | length 753
  Top Layer w10: R1.2@1420.62,1276 1458,1276 1528,1346 1528,1529 1561,1562 1676,1562 1689.37,1548.63 J2.1@1689.37,1448.86
  Top Layer w40: J2.1@1689.37,1448.86 1689.37,1360.63 1700,1350 J3.1@1700,1300
BIN: R4.2 U3.B1 | length 90.2
  Top Layer w10: U3.B1@1804.68,1110 1854,1110 1865,1099 R4.2@1865,1073.62
GND: C2.2 C3.2 C4.2 C7.2 C8.2 C10.2 C11.2 C12.2 C13.2 C14.2 C15.2 C24.2 C25.2 C26.2 C27.2 C28.2 C29.2 J1-3.4 J4-2.2 pad.0@71,395 pad.0@71,1332 pad.0@414,1619 pad.0@475,1618 pad.0@572,1137 pad.0@577,864 pad.0@695,80 pad.0@785,1280 pad.0@786,1339 pad.0@802,467 pad.0@811,835 pad.0@813,1124 pad.0@861.92,467.08 pad.0@891.17,673.08 pad.0@906.92,657.33 pad.0@936.92,839.08 pad.0@946,1400 pad.0@964,1317 pad.0@964,1346 pad.0@976.92,490.92 pad.0@991.92,855.08 pad.0@1030.24,1140.76 pad.0@1046.92,830.92 pad.0@1071,569 pad.0@1162,1118 pad.0@1173.06,398.94 pad.0@1210,1190 pad.0@1254,861 pad.0@1264,458 pad.0@1270,130 pad.0@1295.47,345.47 pad.0@1314,1065 pad.0@1320,130 pad.0@1320,1311 pad.0@1338.94,648.94 pad.0@1341.1,468.9 pad.0@1345,1617 pad.0@1354,752 pad.0@1388.94,649.94 pad.0@1389,1037 pad.0@1389,1063 pad.0@1419,1037 pad.0@1419,1063 pad.0@1424,98 pad.0@1480,98 pad.0@1524.52,404.52 pad.0@1524.53,345.47 pad.0@1630,1129 pad.0@1655,1017 pad.0@1720,977 pad.0@1785,1110 pad.0@1804.68,1129.68 pad.0@1825,732 pad.0@1865,986 pad.0@1888,1616 pad.0@1971,370 pad.0@2296,500 pad.0@2296,1199 R3.1 R4.1 R5.1 R8.1 R9.2 R10.1 R12.1 R13.1 R15.1 R17.1 U2.1 U2.9 U2.11 U2.20 U2.21 U3.B2 U3.C1 U4.1 U4.9 U5.B1 U5.C2 | length 1197.3
  Top Layer w6: pad.0@1865,986 R4.1@1865,1026.38
  Top Layer w10: pad.0@813,1124 R10.1@854.38,1124 ; pad.0@1030.24,1140.76 R9.2@1030.24,1176 ; pad.0@1173.06,398.94 R12.1@1210.31,398.94 ; pad.0@1270,130 R13.1@1270,167.76 ; pad.0@1295.47,345.47 U2.11@1325.35,345.47 ; pad.0@1320,130 R15.1@1320,167.76 ; R3.1@1320,1267.53 R3.1@1320,1268.62 ; C7.2@1338.94,607.56 pad.0@1338.94,648.94 ; U2.9@1341.1,439.96 pad.0@1341.1,468.9 ; C8.2@1388.94,607.56 pad.0@1388.94,649.94 ; pad.0@1424,98 C13.2@1425,132.01 ; pad.0@1480,98 C12.2@1480,152.76 ; U2.20@1494.65,345.47 pad.0@1524.53,345.47 ; U2.1@1494.65,404.52 pad.0@1524.52,404.52
  Top Layer w20: pad.0@414,1619 415,1618 C25.2@415,1580 ; C24.2@475,1580 pad.0@475,1618 ; pad.0@785,1280 C11.2@832.2,1280 ; pad.0@787,1340 C10.2@832.2,1340 ; pad.0@801.92,467.08 C27.2@801.92,511.58 ; pad.0@861.92,467.08 C28.2@861.92,511.58 ; C15.2@936.92,790.32 pad.0@936.92,839.08 ; pad.0@946,1400 C14.2@987.2,1400 ; pad.0@965,1345 C3.2@1006.46,1345 ; pad.0@976.92,490.92 C29.2@976.92,529.46 ; C26.2@991.92,809.57 pad.0@991.92,855.08 ; R17.1@1046.92,788.08 pad.0@1046.92,830.92 ; R8.1@1167.32,1190 pad.0@1210,1190 ; R3.1@1320,1268.62 pad.0@1320,1311 ; pad.0@1630,1129 C4.2@1664.38,1129 ; pad.0@1720,977 C2.2@1720,1015.76
  other v1: 1410,344.49 1359.8,375 1460.2,375 1410,405.51 1016.8,1251.11 1016.8,1282.61
GPOUT: J1-3.9 pad.0@1834,930 pad.0@1878,832 R2.1 U3.A1 | length 3441.9
  Top Layer w10: J1-3.9@350,925 307,925 293,911 293,394.63 346.63,341 1042.63,341 1132,251.63 1132,120.37 1179.52,72.85 1377.78,72.85 1377.93,73 1522.37,73 1540.37,91 1856.37,91 1881,115.63 pad.0@1881,829 ; U3.A1@1804.68,1090.32 1804.68,1057 ; R2.1@1805,1023.62 1804.68,1023.94 1804.68,1057 ; pad.0@1834,930 1834,1047 1824,1057 1804.68,1057
  Bottom Layer w10: pad.0@1834,930 1834,876 pad.0@1878,832
NetC1_1: C1.1 R1.1 U1.5 | length 119.3
  Top Layer w10: R1.1@1373.38,1276 1374.38,1275 C1.1@1374.38,1220 1374.38,1201.62 1390,1186 U1.5@1390,1163.62
NetC1_2: C1.2 J2.2 J3.2 Q1.4 U1.4 | length 320.2
  Top Layer w40: 1467,1218 1512,1218 1594,1300 J3.2@1600,1300 1600,1350 1610.63,1360.63 J2.2@1610.63,1448.86
NetC2_1: C2.1 U3.B3 | length 80.6
  Top Layer w10: C2.1@1720,1063 1720,1090 1727,1097 1738,1097 1751,1110 U3.B3@1765.32,1110
NetC3_1: C3.1 C14.1 J4.1 L1.1 R20.2 U4.8 | length 364.8
  Top Layer w10: J4.1@1175,1029 1228,1029 1238,1039 1238,1276 1217,1297 1186,1297
NetC5_1: C5.1 U2.6 | length 266.8
  Top Layer w10: U2.6@1400.15,439.96 1400.15,500.15 1480,580 1480,600 1503.94,623.94 C5.1@1543.76,623.94
NetC5_2: C5.2 C6.2 C9.2 C16.1 C17.1 C18.1 C19.2 C20.1 U2.2 | length 76.1
  Top Layer w10: U2.2@1478.89,439.96 1554.96,439.96
NetC6_1: C6.1 U2.5 | length 194.4
  Top Layer w10: U2.5@1419.84,439.96 1419.84,497.21 1486.56,563.94 C6.1@1529.39,563.94
NetC7_1: C7.1 C8.1 J7.1 pad.0@1422,565 pad.0@1450,490 U2.4 | length 303.3
  Top Layer w10: U2.4@1439.52,439.96 1439.52,479.52 pad.0@1450,490
  Top Layer w20: pad.0@1422,565 1442,585 1442,606
  Top Layer w40: 1442,606 J7.1@1442,719
  Bottom Layer w20: pad.0@1422,565 1450,537 pad.0@1450,490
